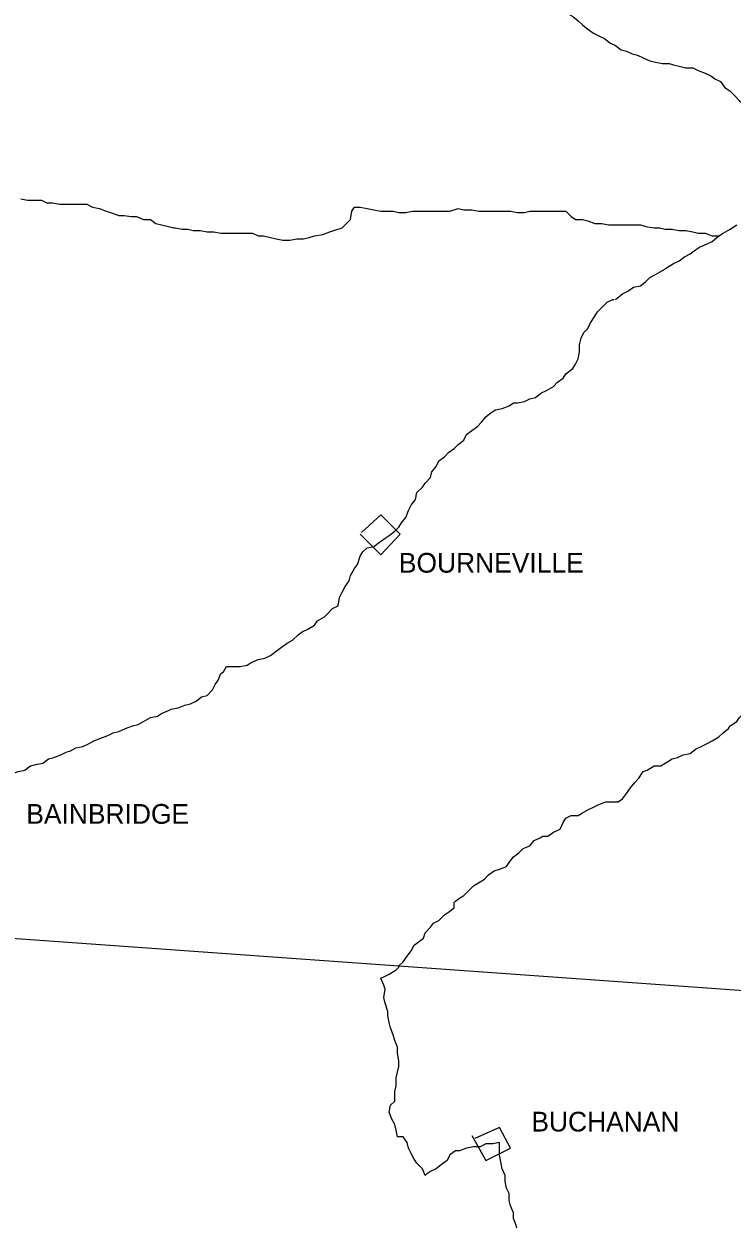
# Model space of a CAD drawing. Extents: x 0 to 34, y 0 to 22.
# Drawn here: x 5.15 to 5.85, y 18.276 to 19.457 of the extents above; entities that cross this region are included whole.
import ezdxf

# ---------------------------------------------------------------- set-up
doc = ezdxf.new("R2010")
doc.units = 0
doc.layers.add('Default', color=7, linetype='Continuous')

msp = doc.modelspace()

# ---------------------------------------------------------------- linework, layer by layer
at = {"layer": 'Default'}
for points in [[(5.6859, 19.4683), (5.6927, 19.4642), (5.6981, 19.4601), (5.7022, 19.456), (5.7077, 19.4519), (5.7131, 19.4478), (5.7186, 19.4451), (5.724, 19.4424), (5.7295, 19.4383), (5.7349, 19.4355), (5.7404, 19.4315), (5.7458, 19.4301), (5.7513, 19.4274), (5.7568, 19.426), (5.7622, 19.4233), (5.769, 19.4205), (5.7745, 19.4192), (5.7813, 19.4178), (5.7881, 19.4178), (5.7922, 19.4165), (5.7922, 19.4165)], [(5.7922, 19.4165), (5.7977, 19.4151), (5.8045, 19.4137), (5.8113, 19.4137), (5.8167, 19.411), (5.8236, 19.4083), (5.829, 19.4055), (5.8331, 19.4028), (5.8386, 19.4001), (5.8426, 19.3946), (5.8481, 19.3906), (5.8522, 19.3865), (5.8576, 19.381), (5.8631, 19.3769), (5.8658, 19.3742), (5.8658, 19.3742)], [(5.1473, 19.2842), (5.1541, 19.2828), (5.1609, 19.2828), (5.1678, 19.2828), (5.1732, 19.2801), (5.1787, 19.2801), (5.1855, 19.2788), (5.1923, 19.2788), (5.2005, 19.2788), (5.2059, 19.2788), (5.2127, 19.2788), (5.2182, 19.276), (5.225, 19.2747), (5.2318, 19.2719), (5.2359, 19.2706), (5.2441, 19.2678), (5.2496, 19.2678), (5.2564, 19.2665), (5.2618, 19.2665), (5.2686, 19.2638), (5.2755, 19.2638), (5.2809, 19.2597), (5.2864, 19.2583), (5.2932, 19.2569), (5.2986, 19.2556), (5.3, 19.2556)], [(5.42, 19.2447), (5.4268, 19.2447), (5.4323, 19.246), (5.4377, 19.2474), (5.4459, 19.2488), (5.4527, 19.2515), (5.4568, 19.2528), (5.465, 19.2556), (5.4691, 19.2597), (5.4732, 19.2638), (5.4745, 19.2719), (5.4772, 19.276), (5.4827, 19.276), (5.4895, 19.2747), (5.4963, 19.2733), (5.5032, 19.2719), (5.5086, 19.2719), (5.5154, 19.2719), (5.5209, 19.2706), (5.5277, 19.2706), (5.5345, 19.2719), (5.5413, 19.2719), (5.5468, 19.2719), (5.5468, 19.2719)], [(5.5468, 19.2719), (5.5536, 19.2719), (5.5604, 19.2719), (5.5672, 19.2719), (5.5713, 19.2719), (5.5795, 19.2747), (5.585, 19.2733), (5.5931, 19.2733), (5.6, 19.2719), (5.6068, 19.2719), (5.6122, 19.2719), (5.619, 19.2719), (5.6259, 19.2719), (5.6313, 19.2719), (5.6381, 19.2706), (5.645, 19.2706), (5.6504, 19.2719), (5.6586, 19.2719), (5.664, 19.2719), (5.6695, 19.2719), (5.6763, 19.2719), (5.6818, 19.2719), (5.6859, 19.2719), (5.6913, 19.2665), (5.6954, 19.2638), (5.7022, 19.2638), (5.7077, 19.2624), (5.7145, 19.2597), (5.7213, 19.2597), (5.7281, 19.2583), (5.7336, 19.2583), (5.7404, 19.2583), (5.7472, 19.2583), (5.7513, 19.2583)], [(5.3, 19.2556), (5.3068, 19.2542), (5.3123, 19.2542), (5.3177, 19.2528), (5.3245, 19.2528), (5.3314, 19.2515), (5.3382, 19.2515), (5.345, 19.2501), (5.3505, 19.2501), (5.3573, 19.2501), (5.3641, 19.2501), (5.3695, 19.2501), (5.3764, 19.2501), (5.3818, 19.2474), (5.3873, 19.2474), (5.3941, 19.246), (5.3995, 19.2447), (5.4064, 19.2433), (5.4132, 19.2433), (5.42, 19.2447), (5.42, 19.2447)], [(5.7513, 19.2583), (5.7595, 19.2583), (5.7649, 19.2569), (5.7731, 19.2556), (5.7786, 19.2556), (5.784, 19.2542), (5.7908, 19.2542), (5.7977, 19.2528), (5.8045, 19.2528), (5.8113, 19.2515), (5.8167, 19.2501), (5.8236, 19.2501), (5.8304, 19.2474), (5.8372, 19.2474), (5.8372, 19.2474)], [(5.8372, 19.2474), (5.8413, 19.2501), (5.8481, 19.2542), (5.8549, 19.2583)], [(5.7349, 19.1847), (5.7418, 19.1901), (5.7472, 19.1929), (5.7527, 19.1969), (5.7595, 19.1983), (5.7649, 19.2024), (5.769, 19.2065), (5.7745, 19.2092), (5.7813, 19.2133), (5.7854, 19.216), (5.7922, 19.2201), (5.7977, 19.2229), (5.8031, 19.2269), (5.8086, 19.2297), (5.814, 19.2338), (5.8181, 19.2365), (5.8249, 19.2392), (5.8304, 19.2419), (5.8372, 19.2474), (5.8372, 19.2474)], [(5.6381, 19.0824), (5.645, 19.0838), (5.6504, 19.0865), (5.6559, 19.0879), (5.6613, 19.092), (5.6668, 19.0947), (5.6736, 19.0988), (5.6777, 19.1029), (5.6831, 19.107), (5.6859, 19.1111), (5.6927, 19.1165), (5.6954, 19.1206), (5.6981, 19.126), (5.6995, 19.1329), (5.6995, 19.1397), (5.7009, 19.1465), (5.7036, 19.152), (5.7077, 19.156), (5.7104, 19.1615), (5.7145, 19.1683), (5.7172, 19.1724), (5.7227, 19.1779), (5.7268, 19.1819), (5.7322, 19.1847), (5.7322, 19.1847), (5.7336, 19.1847)], [(5.5113, 18.9515), (5.5168, 18.9556), (5.5209, 18.9597), (5.5236, 18.9638), (5.5277, 18.9693), (5.5304, 18.9761), (5.5331, 18.9815), (5.5372, 18.987), (5.5386, 18.9938), (5.5441, 18.9992), (5.5468, 19.0033), (5.5522, 19.0088), (5.5536, 19.0142), (5.5577, 19.0197), (5.5604, 19.0252), (5.5659, 19.0292), (5.57, 19.0333), (5.5754, 19.0374), (5.5795, 19.0415), (5.585, 19.0456), (5.5877, 19.0511), (5.5931, 19.0551), (5.5986, 19.0592), (5.6027, 19.0633), (5.6068, 19.0688), (5.6122, 19.0729), (5.6163, 19.0756), (5.6231, 19.077), (5.63, 19.0797), (5.634, 19.0824), (5.6381, 19.0824), (5.6381, 19.0824)], [(5.4827, 18.9529), (5.5032, 18.9324), (5.5222, 18.9529), (5.5032, 18.972), (5.4841, 18.9543)], [(5.3477, 18.8166), (5.3505, 18.822), (5.3573, 18.822), (5.3641, 18.822), (5.3709, 18.8234), (5.375, 18.8261), (5.3818, 18.8288), (5.3886, 18.8302), (5.3941, 18.8329), (5.3995, 18.837), (5.405, 18.8411), (5.4104, 18.8452), (5.4159, 18.8479), (5.4213, 18.8534), (5.4254, 18.8561), (5.4309, 18.8588), (5.4377, 18.8629), (5.4404, 18.867), (5.4473, 18.8711), (5.45, 18.8738), (5.4554, 18.8793), (5.4609, 18.882), (5.4623, 18.8902), (5.465, 18.8956), (5.4677, 18.9011), (5.4718, 18.9065), (5.4732, 18.912), (5.4772, 18.9188), (5.48, 18.9229), (5.4827, 18.9311), (5.4854, 18.9352), (5.4895, 18.9393), (5.4963, 18.9406), (5.5018, 18.9447), (5.5072, 18.9488), (5.5113, 18.9515), (5.5113, 18.9515)], [(5.2959, 18.7797), (5.3027, 18.7811), (5.3095, 18.7838), (5.315, 18.7852), (5.3205, 18.7879), (5.3259, 18.792), (5.3314, 18.7934), (5.3368, 18.7988), (5.3395, 18.8043), (5.3423, 18.8084), (5.345, 18.8152), (5.3477, 18.8166)], [(5.8481, 18.7634), (5.8549, 18.7675), (5.8576, 18.7716), (5.8617, 18.7756), (5.8645, 18.7811), (5.8658, 18.7879), (5.8699, 18.792), (5.874, 18.7961), (5.8781, 18.7975), (5.8795, 18.7975)], [(5.1964, 18.7388), (5.2018, 18.7416), (5.2087, 18.7429), (5.2141, 18.7457), (5.2196, 18.7484), (5.2264, 18.7511), (5.2332, 18.7538), (5.2387, 18.7566), (5.2441, 18.7579), (5.2509, 18.7607), (5.2577, 18.7634), (5.2632, 18.7647), (5.2686, 18.7675), (5.2755, 18.7716), (5.2823, 18.7729), (5.2864, 18.7756), (5.2932, 18.7784), (5.2959, 18.7797)], [(5.664, 18.6543), (5.6681, 18.6543), (5.6736, 18.6584), (5.6804, 18.6611), (5.6831, 18.6679), (5.6859, 18.672), (5.6913, 18.6748), (5.6981, 18.6748), (5.7022, 18.6775), (5.7077, 18.6802), (5.7131, 18.6829), (5.7186, 18.6857), (5.7254, 18.6884), (5.7322, 18.6884), (5.7377, 18.6884), (5.7418, 18.6911), (5.7458, 18.6966), (5.7499, 18.702), (5.754, 18.7075), (5.7581, 18.7116), (5.7622, 18.7184), (5.7663, 18.7197), (5.7731, 18.7238), (5.7799, 18.7238), (5.784, 18.7266), (5.7908, 18.7307), (5.7963, 18.732), (5.8017, 18.7347), (5.8086, 18.7361), (5.814, 18.7402), (5.8195, 18.7429), (5.8249, 18.7457), (5.8304, 18.7484), (5.8372, 18.7525), (5.8413, 18.7566), (5.8467, 18.7607), (5.8481, 18.7634)], [(5.1064, 18.7075), (5.1119, 18.7102), (5.1187, 18.7116), (5.1255, 18.7129), (5.1323, 18.7143), (5.1378, 18.7157), (5.1446, 18.7184), (5.1514, 18.7197), (5.1568, 18.7238), (5.1623, 18.7252), (5.1691, 18.7266), (5.1746, 18.7307), (5.18, 18.732), (5.1868, 18.7347), (5.1923, 18.7375), (5.1964, 18.7388), (5.1964, 18.7388)], [(5.5768, 18.5902), (5.5809, 18.593), (5.585, 18.5957), (5.5904, 18.6011), (5.5945, 18.6052), (5.6013, 18.6093), (5.6054, 18.612), (5.6095, 18.6161), (5.615, 18.6202), (5.6204, 18.6216), (5.6272, 18.6243), (5.63, 18.6284), (5.634, 18.6339), (5.6395, 18.6379), (5.6436, 18.642), (5.6504, 18.6448), (5.6545, 18.6502), (5.6613, 18.6529), (5.6627, 18.6543), (5.664, 18.6543)], [(5.5209, 18.5261), (5.525, 18.5302), (5.5291, 18.5357), (5.5331, 18.5411), (5.5359, 18.5466), (5.5413, 18.5507), (5.5454, 18.5534), (5.5468, 18.5589), (5.5522, 18.5643), (5.555, 18.5684), (5.5604, 18.5711), (5.5659, 18.5766), (5.57, 18.5793), (5.5754, 18.5834), (5.5754, 18.5889), (5.5768, 18.5902)], [(4.8119, 18.5752), (4.9496, 18.567), (5.5209, 18.5261), (6.1521, 18.4811), (6.812, 18.4321)], [(5.5168, 18.4021), (5.5182, 18.4075), (5.5182, 18.4157), (5.5195, 18.4212), (5.5209, 18.4266), (5.5209, 18.4321), (5.5195, 18.4402), (5.5195, 18.4457), (5.5168, 18.4525), (5.5154, 18.458), (5.5127, 18.4648), (5.5113, 18.4702), (5.51, 18.4771), (5.51, 18.4811), (5.5072, 18.4893), (5.5059, 18.4948), (5.5072, 18.503), (5.5059, 18.5071), (5.5032, 18.5139), (5.5059, 18.5152), (5.5113, 18.518), (5.5182, 18.5221), (5.5209, 18.5248), (5.5209, 18.5261)], [(5.5468, 18.3189), (5.5441, 18.3257), (5.5386, 18.3312), (5.5359, 18.3353), (5.5331, 18.3407), (5.5304, 18.3462), (5.5291, 18.3516), (5.525, 18.3571), (5.5195, 18.3571), (5.5182, 18.3639), (5.5168, 18.3693), (5.5141, 18.3748), (5.5113, 18.3816), (5.5127, 18.3884), (5.5168, 18.3925), (5.5168, 18.3993), (5.5168, 18.4021)], [(5.5931, 18.3584), (5.6068, 18.3339), (5.6313, 18.3462), (5.6204, 18.3666), (5.5959, 18.3557)], [(5.6204, 18.3516), (5.6136, 18.3503), (5.6068, 18.3503), (5.6013, 18.3475), (5.5945, 18.3475), (5.5877, 18.3462), (5.5809, 18.3434), (5.5768, 18.3434), (5.5713, 18.3394), (5.5686, 18.3339), (5.5631, 18.3298), (5.5577, 18.3257), (5.5522, 18.323), (5.5481, 18.3203), (5.5468, 18.3189)], [(5.6381, 18.2644), (5.6368, 18.2698), (5.634, 18.2766), (5.634, 18.2821), (5.6313, 18.2889), (5.63, 18.2944), (5.63, 18.3012), (5.6272, 18.3066), (5.6259, 18.3134), (5.6259, 18.3189), (5.6231, 18.3257), (5.6218, 18.3325), (5.6204, 18.3394), (5.6204, 18.3434), (5.6204, 18.3503), (5.6204, 18.3516)]]:
    msp.add_lwpolyline(points, dxfattribs=at)

# ---------------------------------------------------------------- texts
for s, height, p in [('BOURNEVILLE', 0.019502, (5.5209, 18.9147)), ('BAINBRIDGE', 0.0195, (5.1528, 18.6666)), ('BUCHANAN', 0.0195, (5.6518, 18.3625))]:
    msp.add_text(s, height=height, dxfattribs=at).set_placement(p)

doc.saveas('drawing.dxf')
